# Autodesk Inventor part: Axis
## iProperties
Shininess: 65.0
Length Units: 11269
Angle Units: 11279
Time Units: 11290
Mass Units: 11283
Length Display Precision: 3
Angle Display Precision: 2
Created: 2001-11
Part Number: Axis
Document SubType Name: Modeling
Designer: Renu Muthoo
Density: 1 g/cm^3
Density: 0.0
Volumn: 0.0
Area: 0.0
PropertySet Name: Model Information
Control State: 0
Master: False
Checked Out: False
Author: Renu Muthoo
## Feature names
1. Revolution1
